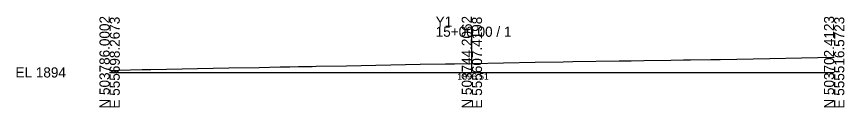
# Model space of a CAD drawing. Extents: x -26 to 1503, y -10 to 5015.
# Drawn here: x -25.7 to 202.8, y 4990.3 to 5015.5 of the extents above; entities that cross this region are included whole.
import ezdxf

# ---------------------------------------------------------------- set-up
doc = ezdxf.new("R2010")
doc.units = 0
for name, color, linetype in [('Default', 7, 'Continuous'), ('Exist Cross Section Cell', 7, 'Continuous'), ('Exist XS Center Line Elevation Label', 7, 'Continuous'), ('Exist XS Ground Line', 7, 'Continuous')]:
    doc.layers.add(name, color=color, linetype=linetype)

msp = doc.modelspace()

# ---------------------------------------------------------------- linework, layer by layer
at = {"layer": 'Exist Cross Section Cell'}
for p, q in [((100, 5000), (100, 5012.66)), ((0, 5000), (100, 5000)), ((100, 5000), (200, 5000))]:
    msp.add_line(p, q, dxfattribs=at)
at = {"layer": 'Exist XS Ground Line'}
for p, q in [((100, 5002.51), (117.43, 5002.82)), ((117.43, 5002.82), (125.2, 5002.96)), ((125.2, 5002.96), (127.87, 5003)), ((127.87, 5003), (140.67, 5003.16)), ((140.67, 5003.16), (142.04, 5003.21)), ((142.04, 5003.21), (143.99, 5003.23)), ((143.99, 5003.23), (147.43, 5003.28)), ((147.43, 5003.28), (154.93, 5003.41)), ((154.93, 5003.41), (158.38, 5003.46)), ((158.38, 5003.46), (160.39, 5003.48)), ((160.39, 5003.48), (165.98, 5003.57)), ((165.98, 5003.57), (168.58, 5003.62)), ((168.58, 5003.62), (182.26, 5003.89)), ((182.26, 5003.89), (190.99, 5004.04)), ((190.99, 5004.04), (200, 5004.22)), ((0, 5000.54), (2.44, 5000.58)), ((2.44, 5000.58), (9.02, 5000.77)), ((9.02, 5000.77), (11.41, 5000.82)), ((11.41, 5000.82), (32.93, 5001.24)), ((32.93, 5001.24), (41.31, 5001.39)), ((41.31, 5001.39), (47.08, 5001.51)), ((47.08, 5001.51), (49.72, 5001.56)), ((49.72, 5001.56), (52.16, 5001.61)), ((52.16, 5001.61), (54.79, 5001.65)), ((54.79, 5001.65), (55.91, 5001.68)), ((55.91, 5001.68), (56.97, 5001.69)), ((56.97, 5001.69), (65.38, 5001.86)), ((65.38, 5001.86), (85.76, 5002.25)), ((85.76, 5002.25), (92.74, 5002.38)), ((92.74, 5002.38), (95.2, 5002.42)), ((95.2, 5002.42), (100, 5002.51))]:
    msp.add_line(p, q, dxfattribs=at)

# ---------------------------------------------------------------- texts
at = {"layer": 'Default'}
msp.add_text('-', height=0.0001, dxfattribs=at).set_placement((0, 5000))
at = {"layer": 'Exist Cross Section Cell'}
for s, p in [('N 503786.0002', (0, 4990)), ('E 555698.2673', (2.8, 4990)), ('N 503744.2062', (100, 4990)), ('E 555607.4198', (102.8, 4990)), ('N 503702.4123', (200, 4990)), ('E 555516.5723', (202.8, 4990))]:
    msp.add_text(s, height=2.8, rotation=90, dxfattribs=at).set_placement(p)
for s, p in [('Y1', (90, 5012.66)), ('15+00.00 / 1', (90, 5009.86)), ('EL 1894', (-26, 4998.6))]:
    msp.add_text(s, height=2.8, dxfattribs=at).set_placement(p)
at = {"layer": 'Exist XS Center Line Elevation Label'}
msp.add_text('1896.51', height=1.8, dxfattribs=at).set_placement((95.97, 4997.98))

doc.saveas('drawing.dxf')
